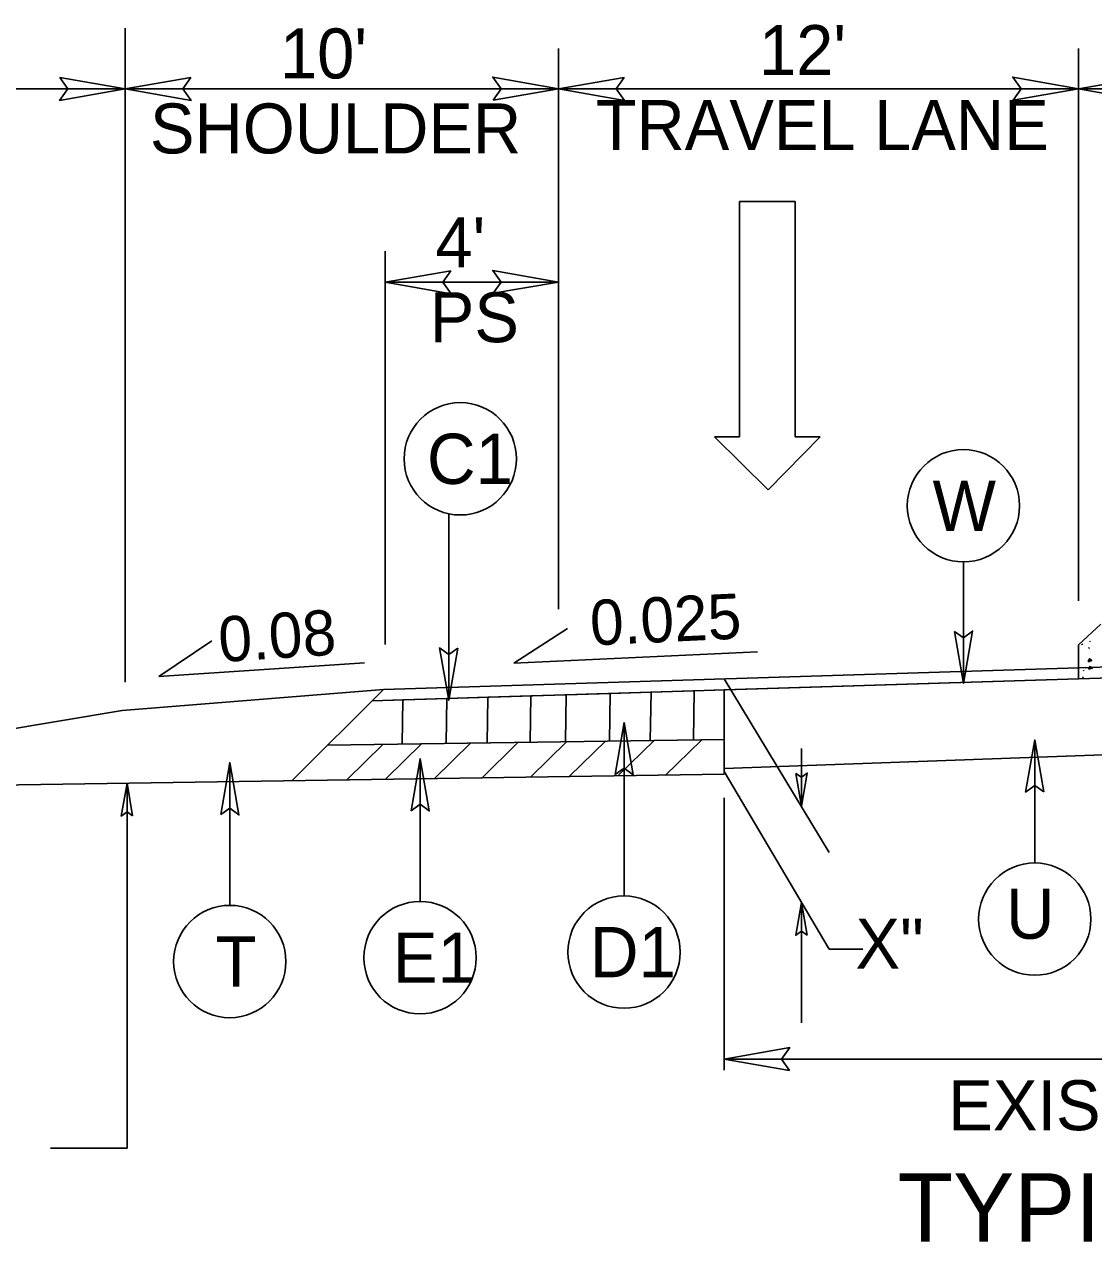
# Model space of a CAD drawing. Extents: x 2176156 to 2177167, y 76401 to 76644.
# Drawn here: x 2177075.16 to 2177099.84, y 76502.12 to 76530.23 of the extents above; entities that cross this region are included whole.
import ezdxf

# ---------------------------------------------------------------- set-up
doc = ezdxf.new("R2010")
doc.units = 0
for name, color, linetype in [('Exist Building', 7, 'Continuous'), ('Exist Building Metal Canopy', 7, 'Continuous'), ('Exist Roads Change in Surface', 7, 'Continuous'), ('Exist Roads Curbs', 7, 'Continuous'), ('Exist Roads EOP Other', 7, 'Continuous'), ('Exist Roads Soil', 7, 'Continuous'), ('Exist Structure Minor Culvert Topo', 7, 'Continuous'), ('Exist Structure Minor Drop Inlet', 7, 'Continuous'), ('Exist Utilities Other Pole CELL', 7, 'Continuous'), ('Model Boundary Lines Text', 7, 'Continuous'), ('Old_Level_1', 7, 'Continuous'), ('Old_Level_3', 7, 'Continuous'), ('Prop North Arrow NAD83 for Plan Sheets CELL', 7, 'Continuous'), ('Sheet Plan CELL', 7, 'Continuous')]:
    doc.layers.add(name, color=color, linetype=linetype)

msp = doc.modelspace()

# ---------------------------------------------------------------- linework, layer by layer
at = {"layer": 'Exist Building'}
for p, q in [((2177091.306, 76512.924), (2177091.306, 76514.875)), ((2177066.344, 76512.553), (2177091.306, 76512.924))]:
    msp.add_line(p, q, dxfattribs=at)
at = {"layer": 'Exist Roads Change in Surface'}
for p, q in [((2177099.566, 76515.932), (2177099.577, 76515.916)), ((2177099.726, 76515.824), (2177099.737, 76515.848)), ((2177099.747, 76516), (2177099.757, 76515.984)), ((2177099.6, 76515.325), (2177099.611, 76515.31)), ((2177099.585, 76515.149), (2177099.595, 76515.173))]:
    msp.add_line(p, q, dxfattribs=at)
for points in [[(2177099.708, 76515.523), (2177099.74, 76515.59), (2177099.793, 76515.55), (2177099.708, 76515.523)], [(2177099.721, 76515.348), (2177099.751, 76515.416), (2177099.805, 76515.377), (2177099.721, 76515.348)]]:
    msp.add_lwpolyline(points, dxfattribs=at)
at = {"layer": 'Exist Roads Curbs'}
for p, q in [((2177099.488, 76515.381), (2177108.163, 76515.651)), ((2177108.163, 76515.401), (2177083.187, 76514.622)), ((2177099.488, 76515.381), (2177083.447, 76514.88)), ((2177099.488, 76515.381), (2177083.447, 76514.88)), ((2177099.488, 76515.131), (2177099.488, 76515.381)), ((2177083.447, 76514.88), (2177083.187, 76514.622))]:
    msp.add_line(p, q, dxfattribs=at)
for points in [[(2177084.91, 76514.676), (2177085.851, 76514.705), (2177086.848, 76514.736), (2177087.662, 76514.762), (2177088.68, 76514.793), (2177089.621, 76514.823), (2177090.619, 76514.854), (2177091.306, 76514.875), (2177099.488, 76515.131)], [(2177083.187, 76514.622), (2177083.892, 76514.644), (2177084.91, 76514.676)]]:
    msp.add_lwpolyline(points, dxfattribs=at)
at = {"layer": 'Exist Roads EOP Other'}
msp.add_line((2177083.447, 76514.88), (2177077.412, 76514.397), dxfattribs=at)
at = {"layer": 'Exist Roads Soil'}
for p, q in [((2177099.488, 76515.912), (2177100.005, 76516.388)), ((2177099.488, 76515.912), (2177099.488, 76515.131)), ((2177083.447, 76514.88), (2177081.33, 76512.776)), ((2177049.46, 76509.739), (2177077.412, 76514.397)), ((2177091.306, 76513.731), (2177082.154, 76513.594))]:
    msp.add_line(p, q, dxfattribs=at)
at = {"layer": 'Exist Structure Minor Drop Inlet'}
for p, q in [((2177091.667, 76520.71), (2177091.667, 76526.142)), ((2177091.667, 76526.142), (2177092.947, 76526.142)), ((2177092.947, 76526.142), (2177092.947, 76520.71)), ((2177092.327, 76519.488), (2177091.085, 76520.71)), ((2177091.085, 76520.71), (2177091.667, 76520.71)), ((2177093.529, 76520.71), (2177092.327, 76519.488)), ((2177092.947, 76520.71), (2177093.529, 76520.71))]:
    msp.add_line(p, q, dxfattribs=at)
at = {"layer": 'Exist Utilities Other Pole CELL'}
for p, q in [((2177086.452, 76515.492), (2177087.692, 76516.288)), ((2177078.261, 76515.182), (2177079.485, 76516.002)), ((2177086.452, 76515.492), (2177092.078, 76515.754)), ((2177078.261, 76515.182), (2177083.007, 76515.496))]:
    msp.add_line(p, q, dxfattribs=at)
at = {"layer": 'Model Boundary Lines Text'}
for p, q in [((2177085.836, 76513.643), (2177085.851, 76514.705)), ((2177086.833, 76513.664), (2177086.848, 76514.736)), ((2177087.647, 76513.676), (2177087.662, 76514.762)), ((2177088.665, 76513.691), (2177088.68, 76514.793)), ((2177089.605, 76513.705), (2177089.621, 76514.823)), ((2177090.602, 76513.72), (2177090.619, 76514.854)), ((2177083.877, 76513.62), (2177083.892, 76514.644)), ((2177084.895, 76513.635), (2177084.91, 76514.676)), ((2177082.603, 76512.8), (2177083.43, 76513.61)), ((2177083.497, 76512.818), (2177084.332, 76513.637)), ((2177084.616, 76512.822), (2177085.451, 76513.641)), ((2177085.706, 76512.831), (2177086.541, 76513.649)), ((2177086.846, 76512.863), (2177087.673, 76513.673)), ((2177087.74, 76512.882), (2177088.575, 76513.7)), ((2177088.859, 76512.886), (2177089.694, 76513.704)), ((2177089.949, 76512.894), (2177090.784, 76513.713))]:
    msp.add_line(p, q, dxfattribs=at)
at = {"layer": 'Old_Level_1'}
for points in [[(2177075.979, 76529.004), (2177077.488, 76528.744), (2177075.97, 76528.476), (2177076.163, 76528.744)], [(2177078.998, 76529.004), (2177077.488, 76528.744), (2177079.006, 76528.476), (2177078.813, 76528.744)], [(2177085.979, 76528.484), (2177087.488, 76528.744), (2177085.97, 76529.012), (2177086.163, 76528.744)], [(2177088.998, 76529.004), (2177087.488, 76528.744), (2177089.006, 76528.476), (2177088.813, 76528.744)], [(2177097.979, 76528.484), (2177099.488, 76528.744), (2177097.97, 76529.012), (2177098.163, 76528.744)], [(2177100.998, 76529.004), (2177099.488, 76528.744), (2177101.006, 76528.476), (2177100.813, 76528.744)], [(2177084.998, 76524.544), (2177083.488, 76524.284), (2177085.006, 76524.015), (2177084.813, 76524.284)], [(2177085.979, 76524.024), (2177087.488, 76524.284), (2177085.97, 76524.552), (2177086.163, 76524.284)], [(2177077.657, 76511.964), (2177077.527, 76512.719), (2177077.393, 76511.96), (2177077.527, 76512.057)], [(2177092.962, 76512.947), (2177093.095, 76512.193), (2177093.227, 76512.952), (2177093.093, 76512.855)], [(2177093.227, 76509.214), (2177093.095, 76509.968), (2177092.963, 76509.209), (2177093.097, 76509.306)], [(2177092.816, 76506.092), (2177091.306, 76506.352), (2177092.824, 76506.62), (2177092.631, 76506.352)]]:
    msp.add_lwpolyline(points, close=True, dxfattribs=at)
at = {"layer": 'Old_Level_3'}
for p, q in [((2177077.488, 76515.053), (2177077.488, 76530.14)), ((2177087.488, 76516.732), (2177087.488, 76529.672)), ((2177099.488, 76517.007), (2177099.488, 76529.672)), ((2177099.488, 76516.931), (2177099.488, 76529.629)), ((2177077.488, 76528.744), (2177065.488, 76528.744)), ((2177077.488, 76528.744), (2177087.488, 76528.744)), ((2177087.488, 76528.744), (2177099.488, 76528.744)), ((2177099.488, 76528.744), (2177108.163, 76528.744)), ((2177083.488, 76515.918), (2177083.488, 76524.993)), ((2177083.488, 76524.284), (2177087.488, 76524.284)), ((2177091.306, 76515.125), (2177093.731, 76511.117)), ((2177093.095, 76512.193), (2177093.095, 76513.521)), ((2177077.527, 76512.719), (2177077.527, 76504.294)), ((2177091.306, 76512.987), (2177093.731, 76508.893)), ((2177091.306, 76512.379), (2177091.306, 76506.098)), ((2177093.095, 76507.192), (2177093.095, 76509.968)), ((2177094.511, 76508.893), (2177093.731, 76508.893)), ((2177115.086, 76506.352), (2177091.306, 76506.352)), ((2177075.76, 76504.294), (2177077.527, 76504.294))]:
    msp.add_line(p, q, dxfattribs=at)
at = {"layer": 'Prop North Arrow NAD83 for Plan Sheets CELL'}
for p, q in [((2177084.953, 76518.936), (2177084.953, 76514.633)), ((2177096.832, 76517.826), (2177096.832, 76515.022)), ((2177088.998, 76510.118), (2177088.998, 76514.119)), ((2177098.478, 76510.879), (2177098.478, 76513.72)), ((2177084.29, 76509.989), (2177084.29, 76513.285)), ((2177079.898, 76509.9), (2177079.898, 76513.196))]:
    msp.add_line(p, q, dxfattribs=at)
for points in [[(2177096.625, 76516.222), (2177096.832, 76515.022), (2177097.045, 76516.228), (2177096.832, 76516.075)], [(2177085.16, 76515.833), (2177084.953, 76514.633), (2177084.74, 76515.84), (2177084.953, 76515.687)], [(2177088.791, 76512.919), (2177088.998, 76514.119), (2177089.211, 76512.912), (2177088.998, 76513.065)], [(2177098.685, 76512.52), (2177098.478, 76513.72), (2177098.265, 76512.514), (2177098.478, 76512.667)], [(2177084.083, 76512.085), (2177084.29, 76513.285), (2177084.503, 76512.079), (2177084.29, 76512.232)], [(2177079.691, 76511.996), (2177079.898, 76513.196), (2177080.111, 76511.989), (2177079.898, 76512.142)]]:
    msp.add_lwpolyline(points, close=True, dxfattribs=at)
for centre in [(2177085.219, 76520.205), (2177096.832, 76519.122), (2177098.478, 76509.583), (2177079.898, 76508.604), (2177084.29, 76508.693), (2177088.998, 76508.822)]:
    msp.add_circle(centre, 1.296, dxfattribs=at)
at = {"layer": 'Sheet Plan CELL'}
msp.add_line((2177091.306, 76513.06), (2177108.163, 76513.671), dxfattribs=at)

# ---------------------------------------------------------------- texts
at = {"layer": 'Exist Building Metal Canopy'}
msp.add_text('TYPICAL SECTION NO.  6', height=1.5766, rotation=0, dxfattribs=at).set_placement((2177095.309, 76502.14))
at = {"layer": 'Exist Structure Minor Culvert Topo'}
for s, height, p in [("10' ", 1.1533, (2177081.058, 76528.982)), ("12'", 1.1533, (2177092.114, 76529.06)), ('TRAVEL LANE', 1.15334, (2177088.344, 76527.33)), ('SHOULDER', 1.1533, (2177078.056, 76527.252)), ("4' ", 1.1533, (2177084.644, 76524.625)), ('PS', 1.1533, (2177084.515, 76522.895)), ("EXIST. PAVEMENT 21'", 1.15334, (2177096.483, 76504.711))]:
    msp.add_text(s, height=height, dxfattribs=at).set_placement(p)
at = {"layer": 'Exist Utilities Other Pole CELL'}
for s, rotation, p in [('0.025', 2.6676, (2177088.238, 76515.898)), ('0.08', 3.7801, (2177079.671, 76515.512))]:
    msp.add_text(s, height=1.0429, rotation=rotation, dxfattribs=at).set_placement(p)
at = {"layer": 'Prop North Arrow NAD83 for Plan Sheets CELL'}
for s, rotation, p in [('C1', 0.0003, (2177084.45, 76519.625)), ('W', 359.9997, (2177096.119, 76518.542)), ('U', 359.9997, (2177097.814, 76509.129)), ('D1', 0.0003, (2177088.212, 76508.242)), ('T', 0.0003, (2177079.571, 76508.024)), ('E1', 0.0003, (2177083.662, 76508.113))]:
    msp.add_text(s, height=1.16, rotation=rotation, dxfattribs=at).set_placement(p)
msp.add_text('X"', height=1.1533, dxfattribs=at).set_placement((2177094.341, 76508.443))

doc.saveas('drawing.dxf')
